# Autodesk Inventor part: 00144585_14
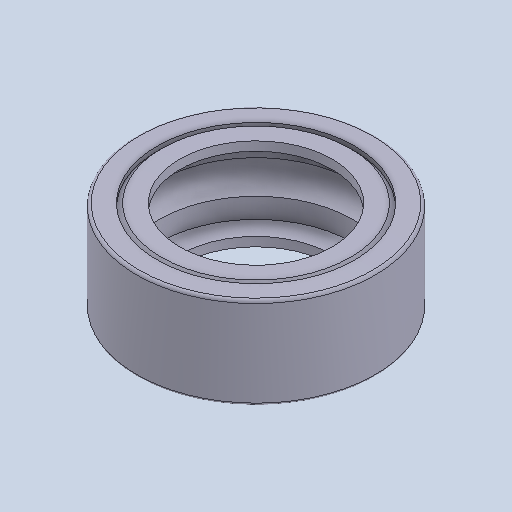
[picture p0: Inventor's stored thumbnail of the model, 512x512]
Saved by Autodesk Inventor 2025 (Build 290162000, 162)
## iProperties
Created: 2021-02
Part Number: 00144585_14
Material: Generico
Document SubType Name: Modeling
Designer: Ryzen5700u
Density: 1 g/cm^3
Appearance: Default
Author: Ryzen5700u
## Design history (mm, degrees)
feature "Solido1"
node "Solido2"
